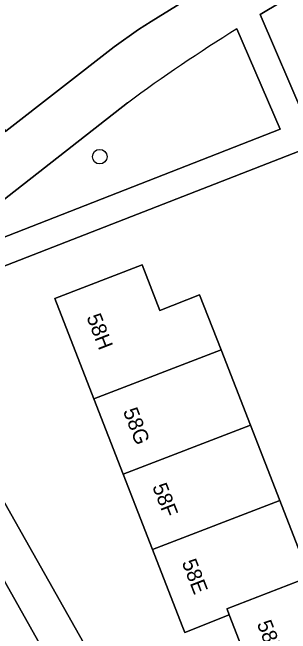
# Model space of a CAD drawing. Extents: x 159680 to 160786, y 387323 to 388340.
# Drawn here: x 159831.48 to 159850.1, y 387740.35 to 387781.89 of the extents above; entities that cross this region are included whole.
import ezdxf

# ---------------------------------------------------------------- set-up
doc = ezdxf.new("R2010")
doc.units = 0
for name, color, linetype in [('IMGEO_Berm_groen', 7, 'Continuous'), ('IMGEO_Boom', 7, 'Continuous'), ('IMGEO_Erf', 7, 'Continuous'), ('IMGEO_Groenvoorziening', 7, 'Continuous'), ('IMGEO_Pand', 7, 'Continuous'), ('IMGEO_Pand_nummerreeks', 7, 'Continuous'), ('IMGEO_Rijbaan_lokaal_gesloten', 7, 'Continuous'), ('IMGEO_Voetpad_open', 7, 'Continuous')]:
    doc.layers.add(name, color=color, linetype=linetype)

msp = doc.modelspace()

# ---------------------------------------------------------------- linework, layer by layer
at = {"layer": 'IMGEO_Berm_groen'}
msp.add_lwpolyline([(159847.442, 387713.648), (159847.883, 387713.881), (159836.437, 387734.091), (159823.476, 387757.109)], dxfattribs=at)
at = {"layer": 'IMGEO_Boom'}
msp.add_circle((159837.326, 387772.241), 0.489, dxfattribs=at)
at = {"layer": 'IMGEO_Erf'}
for points in [[(159882.805, 387771.989), (159877.7, 387770.009), (159872.594, 387768.029), (159867.489, 387766.049), (159862.384, 387764.069), (159857.279, 387762.089), (159855.895, 387761.552), (159856.571, 387759.832), (159854.235, 387758.934), (159853.04, 387761.98), (159851.844, 387765.026), (159854.189, 387765.89), (159851.576, 387772.974), (159824.157, 387762.288)], [(159847.951, 387736.558), (159845.984, 387741.61), (159843.013, 387740.421), (159842.844, 387740.856), (159840.856, 387745.97), (159838.898, 387751.005), (159836.935, 387756.055), (159834.326, 387762.766), (159840.173, 387765.018), (159841.356, 387761.964), (159844.011, 387763.006), (159845.442, 387759.332), (159847.408, 387754.282), (159849.369, 387749.248), (159851.355, 387744.148), (159854.395, 387745.324), (159856.53, 387739.898)], [(159824.569, 387760.364), (159825.014, 387759.589), (159832.352, 387746.607), (159840.566, 387732.077)]]:
    msp.add_lwpolyline(points, dxfattribs=at)
at = {"layer": 'IMGEO_Groenvoorziening'}
msp.add_lwpolyline([(159887.85, 387789.101), (159884.834, 387796.943), (159852.103, 387784.175), (159848.069, 387781.74), (159851.074, 387774.741)], close=True, dxfattribs=at)
for points in [[(159824.934, 387764.525), (159849.396, 387774.084), (159846.501, 387780.786)], [(159839.187, 387775.831), (159825.676, 387765.294)]]:
    msp.add_lwpolyline(points, dxfattribs=at)
msp.add_arc((159904.597, 387687.155), 110.19, 121.81895, 126.41381, dxfattribs=at)
at = {"layer": 'IMGEO_Pand'}
for points in [[(159844.011, 387763.006), (159841.356, 387761.964), (159840.173, 387765.018), (159834.326, 387762.766), (159836.935, 387756.055), (159845.442, 387759.332)], [(159845.442, 387759.332), (159836.935, 387756.055), (159838.898, 387751.005), (159847.408, 387754.282)], [(159847.408, 387754.282), (159838.898, 387751.005), (159840.856, 387745.97), (159849.369, 387749.248)], [(159849.369, 387749.248), (159840.856, 387745.97), (159842.844, 387740.856), (159843.013, 387740.421), (159845.984, 387741.61), (159845.844, 387741.969), (159845.828, 387742.01), (159851.355, 387744.148)], [(159854.395, 387745.324), (159851.355, 387744.148), (159845.828, 387742.01), (159845.844, 387741.969), (159845.984, 387741.61), (159847.951, 387736.558), (159856.53, 387739.898)]]:
    msp.add_lwpolyline(points, close=True, dxfattribs=at)
at = {"layer": 'IMGEO_Rijbaan_lokaal_gesloten'}
msp.add_lwpolyline([(159828.926, 387775.861), (159829.48, 387775.93), (159831.047, 387773.947), (159838.282, 387779.58), (159839.919, 387780.743), (159840.766, 387781.286), (159844.166, 387783.389), (159849.485, 387786.622), (159850.217, 387787.047), (159850.661, 387787.323), (159851.392, 387787.722)], dxfattribs=at)
at = {"layer": 'IMGEO_Voetpad_open'}
for points in [[(159880.407, 387799.243), (159871.972, 387795.937), (159872.655, 387794.127), (159870.067, 387793.127), (159869.348, 387794.92), (159861.835, 387791.989), (159855.16, 387789.388), (159856.085, 387787.023), (159851.793, 387785.348), (159850.661, 387787.323), (159850.217, 387787.047), (159849.485, 387786.622), (159844.166, 387783.389), (159840.766, 387781.286), (159839.919, 387780.743), (159838.282, 387779.58), (159831.047, 387773.947), (159824.096, 387768.535)], [(159846.501, 387780.786), (159849.396, 387774.084), (159824.934, 387764.525)], [(159825.676, 387765.294), (159839.187, 387775.831)], [(159824.157, 387762.288), (159851.576, 387772.974)], [(159866.365, 387688.698), (159861.884, 387695.822), (159856.385, 387704.612), (159855.275, 387706.413), (159852.398, 387711.107), (159851.67, 387712.351), (159849.124, 387716.699), (159840.566, 387732.077), (159832.352, 387746.607), (159825.014, 387759.589), (159823.476, 387757.109), (159836.437, 387734.091), (159847.883, 387713.881), (159847.442, 387713.648)]]:
    msp.add_lwpolyline(points, dxfattribs=at)
msp.add_lwpolyline([(159848.069, 387781.74), (159852.103, 387784.175), (159884.834, 387796.943), (159887.85, 387789.101), (159851.074, 387774.741)], close=True, dxfattribs=at)
msp.add_arc((159904.597, 387687.155), 110.19, 121.81895, 126.41381, dxfattribs=at)

# ---------------------------------------------------------------- texts
at = {"layer": 'IMGEO_Pand_nummerreeks'}
for s, rotation, p in [('58H', 291.2451, (159836.421, 387761.517)), ('58G', 291.2451, (159838.867, 387755.226)), ('58F', 291.2451, (159840.828, 387750.182)), ('58E', 291.2451, (159842.801, 387745.108)), ('58D', 291.2737, (159847.826, 387741.013))]:
    msp.add_text(s, height=1, rotation=rotation, dxfattribs=at).set_placement(p)

doc.saveas('drawing.dxf')
